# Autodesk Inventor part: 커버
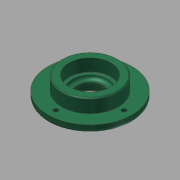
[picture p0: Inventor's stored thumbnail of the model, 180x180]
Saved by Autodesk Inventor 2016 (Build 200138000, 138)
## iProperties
Company: 한국ATC센터
Created: 2014-10
Part Number: 커버
Document SubType Name: Modeling
Designer: KYOUNG IL JANG
Density: 7.86 g/cm^3
Mass: 351.567 g
Surface Area: 161.165 cm^2
Volume: 44.7286 cm^3
Material: 강철, 연강
Appearance: 강철
Author: KYOUNG IL JANG
Revision Number: 1
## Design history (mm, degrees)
sketch "스케치1"
  geometry: C1 r 40 at (0, 0); 1 further point
  constraints: 1 centre point, 1 coincident
  dimensions: "d0" = 80 diameter of C1
extrude "돌출1" new body sketch "스케치1" distance "d1" = 7; taper "d2" = 0 deg
sketch "스케치2"
  geometry: C1 r 27 at (0, 0); 1 further point
  constraints: 1 centre point, 1 coincident
  dimensions: "d3" = 54 diameter of C1
extrude "돌출2" join sketch "스케치2" distance "d4" = 13; taper "d5" = 0 deg
sketch "스케치3"
  geometry: C1 r 20 at (0, 0); 1 further point
  constraints: 1 centre point, 1 coincident
  dimensions: "d6" = 40 diameter of C1
extrude "돌출3" join sketch "스케치3" distance "d7" = 5; taper "d8" = 0 deg
hole "구멍1" diameter "d11" = 25; stored, may be unused: countersink angle "d15" = 90 deg, drill point angle "d17" = 118 deg; dims "d9" = 10, "d10" = 10, "d12" = 6, "d13" = 32, "d14" = 8.3, "d16" = 8
hole "구멍2" diameter "d20" = 34; stored, may be unused: countersink angle "d24" = 90 deg, drill point angle "d26" = 0 deg; dims "d18" = 10, "d19" = 10, "d21" = 6, "d22" = 40, "d23" = 12, "d25" = 3
fillet "모깎기2" dims "d34" = 3
fillet "모깎기1" dims "d27" = 0.3
chamfer "모따기1" distance "d28" = 1; stored, may be unused: second distance "d29" = 2, angle "d30" = 45 deg
chamfer "모따기2" distance "d31" = 1.2; stored, may be unused: second distance "d32" = 2, angle "d33" = 30 deg
sketch "스케치4" dims "d35" = 65
  geometry: 3 further points
  constraints: 2 horizontal alignment, 1 coincident, 2 other
hole "구멍3" sketch "스케치4" at (32.5, 0) diameter "d36" = 4.5; stored, may be unused: countersink angle "d40" = 90 deg, drill point angle "d42" = 118 deg; dims "d37" = 6, "d38" = 8, "d39" = 4.4, "d41" = 13
node "솔리드1"
pattern_circular "원형 패턴1" dims angle "d44" = 360 deg
